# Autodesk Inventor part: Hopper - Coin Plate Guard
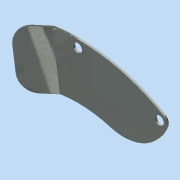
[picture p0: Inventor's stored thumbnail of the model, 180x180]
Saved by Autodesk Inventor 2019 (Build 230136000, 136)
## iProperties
Created: 2005-11
Part Number: Hopper - Coin Plate Guard
Document SubType Name: Sheet Metal
Designer: floress
Material: Steel, Mild
Density: 7.85 g/cm^3
Sheet Metal Rule: Default
Appearance: Zinc
Flat Pattern Width: 5.68731 cm
Flat Pattern Length: 2.82331 cm
Flat Pattern Area: 16.057 cm^2
Sheet Metal Width: 2.239 in
Sheet Metal Length: 1.112 in
Sheet Metal Area: 2.489 in^2
Author: floress
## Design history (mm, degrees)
node "Face1"
  sketch "Sketch1"
    geometry: L1 (-21.024, 52.273)-(-17.803, 30.36); C1 r 1.778 at (-10.983, 49.992); C2 r 1.778 at (22.038, 41.144); A1 r 3.014 centre (22.038, 41.144) between (24.861, 40.088) and (23.545, 43.755); A2 r 46.908 centre (-10.983, -16.05) between (2.396, 28.91) and (-17.803, 30.36); A3 r 18.388 centre (7.64, 46.534) between (2.396, 28.91) and (24.861, 40.088); A4 r 69.056 centre (-10.983, -16.05) between (23.545, 43.755) and (-21.024, 52.273)
    constraints: 8 point on circle, 6 centre point, 2 coincident, 2 end point, 2 tangent, 1 equal radius
    dimensions: "d1" = 3.556 diameter of C1
node "Flange1"
feature "Corner Round1" dims "d10" = 6.35
body "Solid1"
face "Plate1" dims "d11" = 0.79375 (= Thickness)
sketch "Sketch2"
  geometry: L1 through (11.074, 0) direction (1, 0); L2 (22.148, 0)-(22.148, 12.7); L3 (22.148, 12.7)-(0, 12.7); L4 through (0, 6.35) direction (-1.97e-16, -1)
  constraints: 6 end point, 1 horizontal, 1 perpendicular, 1 vertical
face "Plate2" dims "d3" = 0.79375 (= BendReliefWidth), "d5" = 1.5875 (= MinimumRemnant), "d7" = 12.7, "d8" = 30 deg, "d9" = 0.79375 (= BendRadius), "d11" = 0.79375 (= Thickness)
bend "Bend1" dims "d3" = 0.79375 (= BendReliefWidth), "d4" = 0.39687 (= BendReliefDepth), "d5" = 1.5875 (= MinimumRemnant), "d6" = 0.79375 (= BendRadius), "d7" = 12.7, "d8" = 30 deg, "d9" = 0.79375 (= BendRadius), "d11" = 0.79375 (= Thickness), "SeamGap" = 0.00508
feature "Definition1"
other parameters: "Thickness" = 0.79375, "BendRadius" = 0.79375 (= Thickness), "BendReliefWidth" = 0.79375 (= Thickness), "BendReliefDepth" = 0.39687 (= 0.5 x Thickness), "CornerReliefSize" = 3.175 (= 4 x Thickness), "MinimumRemnant" = 1.5875 (= 2 x Thickness), "TransitionRadius" = 0.79375 (= BendRadius), "d0" = 0.79375, "d2" = 0.79375 (= BendRadius), "JacobiRadiusSize" = 0.79375 (= Thickness), "GapSize" = 0.79375 (= Thickness), "BendRadius" = 0.79375, "BendReliefDepth" = 0.39687, "BendReliefWidth" = 0.79375, "CornerReliefSize" = 3.175, "GapSize" = 0.79375, "JacobiRadiusSize" = 0.79375, "MinimumRemnant" = 1.5875, "Thickness" = 0.79375, "TransitionRadius" = 0.79375
